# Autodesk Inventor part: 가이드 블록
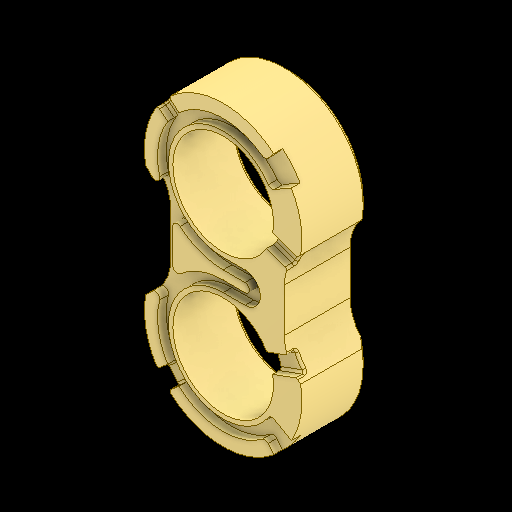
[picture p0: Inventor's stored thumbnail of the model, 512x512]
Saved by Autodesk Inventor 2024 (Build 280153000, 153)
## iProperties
Created: 2025-10
Part Number: 가이드 블록
Material: 강철, 주조
Document SubType Name: Modeling
Designer: EDU03
Density: 7.85 g/cm^3
Appearance: 기본값
Author: jhkim
Sending System: Autodesk Inventor 2026
Preprocessor: ST-DEVELOPER v20.1
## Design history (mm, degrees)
node "가이드 블록1"
node "솔리드2"
node "솔리드1"
